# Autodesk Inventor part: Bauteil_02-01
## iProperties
Created: 2007-04
Part Number: Bauteil_02-01
Document SubType Name: Modeling
Designer: Sascha Fleischer
Author: Sascha Fleischer
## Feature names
1. Abgeleiteter Körper1 [Tagging]
